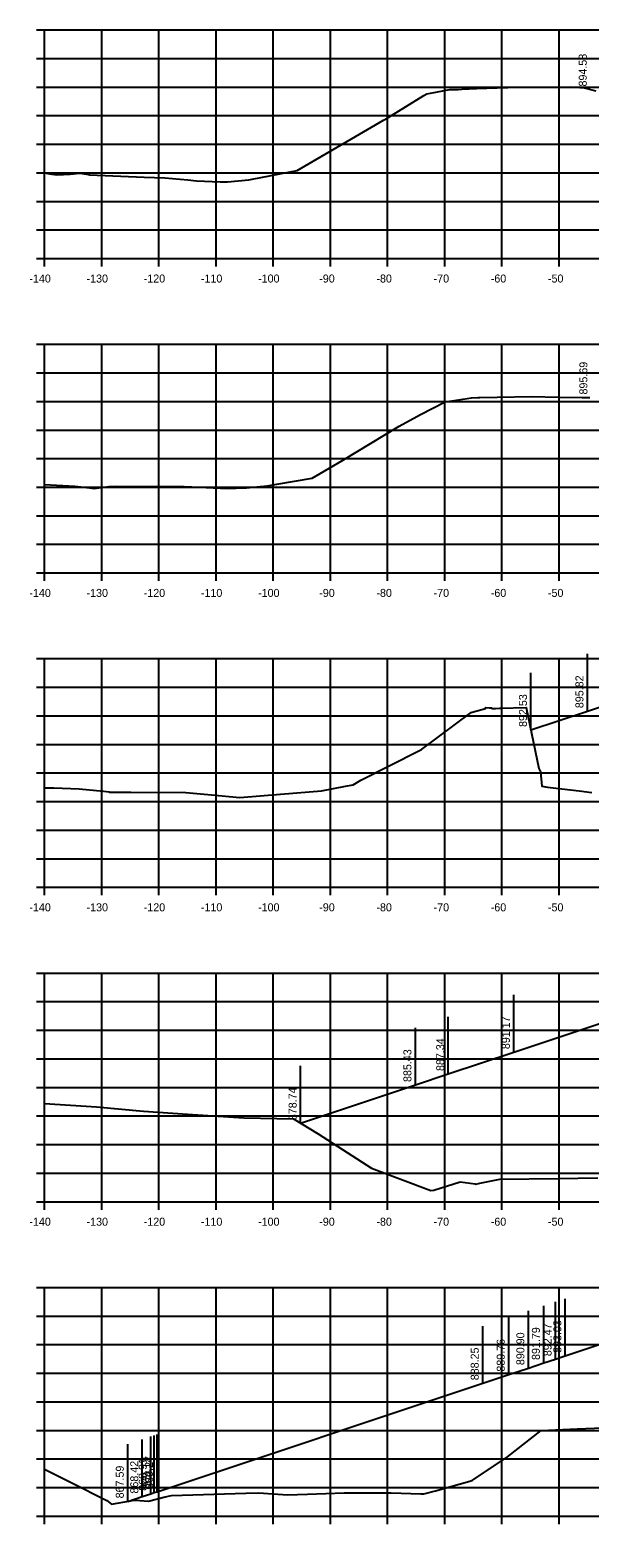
# Model space of a CAD drawing. Extents: x 1098669 to 1198896, y 698679 to 704410.
# Drawn here: x 1111853 to 1111950.8, y 701694.6 to 701956 of the extents above; entities that cross this region are included whole.
import ezdxf

# ---------------------------------------------------------------- set-up
doc = ezdxf.new("R2010")
doc.units = 0
for name, color, linetype in [('59', 7, 'Continuous'), ('Proposed Surface', 7, 'Continuous'), ('R_Axis', 7, 'Continuous'), ('R_Axis Annot', 7, 'Continuous'), ('R_Fin Surface', 7, 'Continuous'), ('R_Grid', 7, 'Continuous'), ('R_Xsect Elev', 7, 'Continuous')]:
    doc.layers.add(name, color=color, linetype=linetype)

msp = doc.modelspace()

# ---------------------------------------------------------------- linework, layer by layer
at = {"layer": 'Proposed Surface'}
for points in [[(1111855.55, 701931.03), (1111856.41, 701930.87), (1111857.69, 701930.65), (1111860, 701930.8), (1111861.69, 701930.98), (1111862.89, 701930.78), (1111863.41, 701930.66), (1111872.98, 701930.25), (1111876.57, 701930.13), (1111880.63, 701929.79), (1111882.09, 701929.64), (1111886.24, 701929.47), (1111887.4, 701929.42), (1111887.53, 701929.44), (1111891.26, 701929.8), (1111891.83, 701929.9), (1111899.74, 701931.41), (1111914.84, 701940.21), (1111915.49, 701940.59), (1111921.87, 701944.52), (1111922.42, 701944.84), (1111923.05, 701944.96), (1111926.42, 701945.57), (1111927.9, 701945.61), (1111928.5, 701945.64), (1111931.1, 701945.75), (1111938.38, 701945.99), (1111940.71, 701946.02), (1111947.5, 701946.08), (1111949.15, 701945.93), (1111949.94, 701945.88), (1111951.98, 701945.39)], [(1111855.55, 701876.51), (1111860.83, 701876.18), (1111863.39, 701875.93), (1111864.23, 701875.8), (1111865.04, 701875.92), (1111866.87, 701876.17), (1111867.73, 701876.16), (1111868.09, 701876.2), (1111879.29, 701876.12), (1111879.96, 701876.12), (1111881.3, 701876.07), (1111887.56, 701875.81), (1111890.59, 701875.9), (1111890.72, 701875.9), (1111890.84, 701875.91), (1111894.49, 701876.29), (1111896.16, 701876.57), (1111902.37, 701877.59), (1111907.51, 701880.65), (1111917.59, 701886.73), (1111921.28, 701888.72), (1111925.61, 701890.98), (1111928.69, 701891.45), (1111930.24, 701891.68), (1111931.3, 701891.69), (1111931.65, 701891.69), (1111934.73, 701891.76), (1111940.72, 701891.9), (1111945.44, 701891.8), (1111949.59, 701891.74), (1111950.9, 701891.74)], [(1111855.55, 701823.45), (1111857.18, 701823.43), (1111861.59, 701823.23), (1111865.84, 701822.82), (1111866.35, 701822.81), (1111866.82, 701822.74), (1111866.84, 701822.69), (1111870.62, 701822.67), (1111880.28, 701822.63), (1111884.72, 701822.23), (1111889.68, 701821.75), (1111896.83, 701822.34), (1111904.01, 701822.92), (1111908.16, 701823.72), (1111909.51, 701823.97), (1111910.88, 701824.75), (1111921.1, 701829.94), (1111921.45, 701830.16), (1111930.17, 701836.61), (1111930.19, 701836.61), (1111930.33, 701836.66), (1111932.67, 701837.31), (1111932.75, 701837.48), (1111933.37, 701837.4), (1111933.69, 701837.41), (1111933.75, 701837.31), (1111934.39, 701837.31), (1111935.1, 701837.38), (1111935.3, 701837.39), (1111939.8, 701837.48), (1111942.01, 701826.83), (1111942.27, 701826.22), (1111942.51, 701823.73), (1111943.49, 701823.54), (1111949.06, 701822.9), (1111951.26, 701822.61)], [(1111855.55, 701768.2), (1111864.64, 701767.62), (1111872.86, 701766.88), (1111880.52, 701766.36), (1111890.37, 701765.69), (1111899.11, 701765.5), (1111903.4, 701762.91), (1111912.71, 701756.88), (1111923.1, 701752.98), (1111923.65, 701753.02), (1111928.23, 701754.48), (1111930.87, 701754.13), (1111930.97, 701754.12), (1111931.67, 701754.26), (1111935.2, 701754.99), (1111945.38, 701755.1), (1111952.3, 701755.23)], [(1111855.55, 701704.22), (1111860.2, 701701.9), (1111866.41, 701698.77), (1111867.27, 701698.14), (1111870.6, 701698.69), (1111871.15, 701698.81), (1111871.43, 701698.79), (1111873.71, 701698.67), (1111876.63, 701699.4), (1111877.74, 701699.63), (1111890.77, 701700.03), (1111893.04, 701700.09), (1111894.63, 701699.98), (1111898.03, 701699.76), (1111901.53, 701699.86), (1111907.94, 701700.12), (1111908.08, 701700.12), (1111916.17, 701700.08), (1111921.35, 701699.95), (1111921.9, 701699.91), (1111923.9, 701700.47), (1111930.31, 701702.27), (1111936.52, 701706.4), (1111942.38, 701711.03), (1111948.71, 701711.3), (1111953.23, 701711.49)]]:
    msp.add_lwpolyline(points, dxfattribs=at)
at = {"layer": 'R_Axis'}
for p, q in [((1111854.15, 701956.03), (1111855.55, 701956.03)), ((1111855.55, 701916.03), (1111855.55, 701956.03)), ((1111854.15, 701951.03), (1111855.55, 701951.03)), ((1111854.15, 701946.03), (1111855.55, 701946.03)), ((1111854.15, 701941.03), (1111855.55, 701941.03)), ((1111854.15, 701936.03), (1111855.55, 701936.03)), ((1111854.15, 701931.03), (1111855.55, 701931.03)), ((1111854.15, 701926.03), (1111855.55, 701926.03)), ((1111854.15, 701921.03), (1111855.55, 701921.03)), ((1111854.15, 701916.03), (1111855.55, 701916.03)), ((1111855.55, 701916.03), (1112135.55, 701916.03)), ((1111855.55, 701914.63), (1111855.55, 701916.03)), ((1111865.55, 701914.63), (1111865.55, 701916.03)), ((1111875.55, 701914.63), (1111875.55, 701916.03)), ((1111885.55, 701914.63), (1111885.55, 701916.03)), ((1111895.55, 701914.63), (1111895.55, 701916.03)), ((1111905.55, 701914.63), (1111905.55, 701916.03)), ((1111915.55, 701914.63), (1111915.55, 701916.03)), ((1111925.55, 701914.63), (1111925.55, 701916.03)), ((1111935.55, 701914.63), (1111935.55, 701916.03)), ((1111945.55, 701914.63), (1111945.55, 701916.03)), ((1111854.15, 701901.03), (1111855.55, 701901.03)), ((1111855.55, 701861.03), (1111855.55, 701901.03)), ((1111854.15, 701896.03), (1111855.55, 701896.03)), ((1111854.15, 701891.03), (1111855.55, 701891.03)), ((1111854.15, 701886.03), (1111855.55, 701886.03)), ((1111854.15, 701881.03), (1111855.55, 701881.03)), ((1111854.15, 701876.03), (1111855.55, 701876.03)), ((1111854.15, 701871.03), (1111855.55, 701871.03)), ((1111854.15, 701866.03), (1111855.55, 701866.03)), ((1111854.15, 701861.03), (1111855.55, 701861.03)), ((1111855.55, 701861.03), (1112135.55, 701861.03)), ((1111855.55, 701859.63), (1111855.55, 701861.03)), ((1111865.55, 701859.63), (1111865.55, 701861.03)), ((1111875.55, 701859.63), (1111875.55, 701861.03)), ((1111885.55, 701859.63), (1111885.55, 701861.03)), ((1111895.55, 701859.63), (1111895.55, 701861.03)), ((1111905.55, 701859.63), (1111905.55, 701861.03)), ((1111915.55, 701859.63), (1111915.55, 701861.03)), ((1111925.55, 701859.63), (1111925.55, 701861.03)), ((1111935.55, 701859.63), (1111935.55, 701861.03)), ((1111945.55, 701859.63), (1111945.55, 701861.03)), ((1111854.15, 701846.03), (1111855.55, 701846.03)), ((1111855.55, 701806.03), (1111855.55, 701846.03)), ((1111854.15, 701841.03), (1111855.55, 701841.03)), ((1111854.15, 701836.03), (1111855.55, 701836.03)), ((1111854.15, 701831.03), (1111855.55, 701831.03)), ((1111854.15, 701826.03), (1111855.55, 701826.03)), ((1111854.15, 701821.03), (1111855.55, 701821.03)), ((1111854.15, 701816.03), (1111855.55, 701816.03)), ((1111854.15, 701811.03), (1111855.55, 701811.03)), ((1111854.15, 701806.03), (1111855.55, 701806.03)), ((1111855.55, 701806.03), (1112135.55, 701806.03)), ((1111855.55, 701804.63), (1111855.55, 701806.03)), ((1111865.55, 701804.63), (1111865.55, 701806.03)), ((1111875.55, 701804.63), (1111875.55, 701806.03)), ((1111885.55, 701804.63), (1111885.55, 701806.03)), ((1111895.55, 701804.63), (1111895.55, 701806.03)), ((1111905.55, 701804.63), (1111905.55, 701806.03)), ((1111915.55, 701804.63), (1111915.55, 701806.03)), ((1111925.55, 701804.63), (1111925.55, 701806.03)), ((1111935.55, 701804.63), (1111935.55, 701806.03)), ((1111945.55, 701804.63), (1111945.55, 701806.03)), ((1111854.15, 701791.03), (1111855.55, 701791.03)), ((1111855.55, 701751.03), (1111855.55, 701791.03)), ((1111854.15, 701786.03), (1111855.55, 701786.03)), ((1111854.15, 701781.03), (1111855.55, 701781.03)), ((1111854.15, 701776.03), (1111855.55, 701776.03)), ((1111854.15, 701771.03), (1111855.55, 701771.03)), ((1111854.15, 701766.03), (1111855.55, 701766.03)), ((1111854.15, 701761.03), (1111855.55, 701761.03)), ((1111854.15, 701756.03), (1111855.55, 701756.03)), ((1111854.15, 701751.03), (1111855.55, 701751.03)), ((1111855.55, 701751.03), (1112135.55, 701751.03)), ((1111855.55, 701749.63), (1111855.55, 701751.03)), ((1111865.55, 701749.63), (1111865.55, 701751.03)), ((1111875.55, 701749.63), (1111875.55, 701751.03)), ((1111885.55, 701749.63), (1111885.55, 701751.03)), ((1111895.55, 701749.63), (1111895.55, 701751.03)), ((1111905.55, 701749.63), (1111905.55, 701751.03)), ((1111915.55, 701749.63), (1111915.55, 701751.03)), ((1111925.55, 701749.63), (1111925.55, 701751.03)), ((1111935.55, 701749.63), (1111935.55, 701751.03)), ((1111945.55, 701749.63), (1111945.55, 701751.03)), ((1111854.15, 701736.03), (1111855.55, 701736.03)), ((1111855.55, 701696.03), (1111855.55, 701736.03)), ((1111854.15, 701731.03), (1111855.55, 701731.03)), ((1111854.15, 701726.03), (1111855.55, 701726.03)), ((1111854.15, 701721.03), (1111855.55, 701721.03)), ((1111854.15, 701716.03), (1111855.55, 701716.03)), ((1111854.15, 701711.03), (1111855.55, 701711.03)), ((1111854.15, 701706.03), (1111855.55, 701706.03)), ((1111854.15, 701701.03), (1111855.55, 701701.03)), ((1111854.15, 701696.03), (1111855.55, 701696.03)), ((1111855.55, 701696.03), (1112135.55, 701696.03)), ((1111855.55, 701694.63), (1111855.55, 701696.03)), ((1111865.55, 701694.63), (1111865.55, 701696.03)), ((1111875.55, 701694.63), (1111875.55, 701696.03)), ((1111885.55, 701694.63), (1111885.55, 701696.03)), ((1111895.55, 701694.63), (1111895.55, 701696.03)), ((1111905.55, 701694.63), (1111905.55, 701696.03)), ((1111915.55, 701694.63), (1111915.55, 701696.03)), ((1111925.55, 701694.63), (1111925.55, 701696.03)), ((1111935.55, 701694.63), (1111935.55, 701696.03)), ((1111945.55, 701694.63), (1111945.55, 701696.03))]:
    msp.add_line(p, q, dxfattribs=at)
at = {"layer": 'R_Fin Surface'}
for points in [[(1111940.62, 701833.56), (1111950.5, 701836.85), (1111954.69, 701838.25), (1111958.75, 701839.6), (1111972.05, 701844.04), (1111977.05, 701843.94), (1111980.05, 701843.88), (1111980.55, 701843.88), (1111981.55, 701843.4), (1111995.55, 701843.68), (1112009.55, 701843.4), (1112010.55, 701843.88), (1112011.05, 701843.88), (1112014.05, 701843.94), (1112019.05, 701844.04), (1112106.87, 701814.76)], [(1111900.33, 701764.77), (1111920.41, 701771.45), (1111926.15, 701773.37), (1111937.63, 701777.2), (1111972.05, 701788.68), (1111977.05, 701788.58), (1111980.05, 701788.52), (1111980.55, 701788.52), (1111981.55, 701788.04), (1111995.55, 701788.32), (1112009.55, 701788.04), (1112010.55, 701788.52), (1112011.05, 701788.52), (1112014.05, 701788.58), (1112019.05, 701788.68), (1112093.91, 701763.73)], [(1111870.1, 701698.61), (1111872.63, 701699.45), (1111874.11, 701699.94), (1111874.74, 701700.15), (1111875.21, 701700.3), (1111932.18, 701719.27), (1111936.73, 701720.78), (1111940.17, 701721.92), (1111942.88, 701722.82), (1111944.92, 701723.49), (1111946.63, 701724.06), (1111962.48, 701729.37)]]:
    msp.add_lwpolyline(points, dxfattribs=at)
at = {"layer": 'R_Grid'}
for p, q in [((1111855.55, 701956.03), (1112135.55, 701956.03)), ((1111855.55, 701916.03), (1111855.55, 701956.03)), ((1111865.55, 701916.03), (1111865.55, 701956.03)), ((1111875.55, 701916.03), (1111875.55, 701956.03)), ((1111885.55, 701916.03), (1111885.55, 701956.03)), ((1111895.55, 701916.03), (1111895.55, 701956.03)), ((1111905.55, 701916.03), (1111905.55, 701956.03)), ((1111915.55, 701916.03), (1111915.55, 701956.03)), ((1111925.55, 701916.03), (1111925.55, 701956.03)), ((1111935.55, 701916.03), (1111935.55, 701956.03)), ((1111945.55, 701916.03), (1111945.55, 701956.03)), ((1111855.55, 701951.03), (1112135.55, 701951.03)), ((1111855.55, 701946.03), (1112135.55, 701946.03)), ((1111855.55, 701941.03), (1112135.55, 701941.03)), ((1111855.55, 701936.03), (1112135.55, 701936.03)), ((1111855.55, 701931.03), (1112135.55, 701931.03)), ((1111855.55, 701926.03), (1112135.55, 701926.03)), ((1111855.55, 701921.03), (1112135.55, 701921.03)), ((1111855.55, 701916.03), (1112135.55, 701916.03)), ((1111855.55, 701901.03), (1112135.55, 701901.03)), ((1111855.55, 701861.03), (1111855.55, 701901.03)), ((1111865.55, 701861.03), (1111865.55, 701901.03)), ((1111875.55, 701861.03), (1111875.55, 701901.03)), ((1111885.55, 701861.03), (1111885.55, 701901.03)), ((1111895.55, 701861.03), (1111895.55, 701901.03)), ((1111905.55, 701861.03), (1111905.55, 701901.03)), ((1111915.55, 701861.03), (1111915.55, 701901.03)), ((1111925.55, 701861.03), (1111925.55, 701901.03)), ((1111935.55, 701861.03), (1111935.55, 701901.03)), ((1111945.55, 701861.03), (1111945.55, 701901.03)), ((1111855.55, 701896.03), (1112135.55, 701896.03)), ((1111855.55, 701891.03), (1112135.55, 701891.03)), ((1111855.55, 701886.03), (1112135.55, 701886.03)), ((1111855.55, 701881.03), (1112135.55, 701881.03)), ((1111855.55, 701876.03), (1112135.55, 701876.03)), ((1111855.55, 701871.03), (1112135.55, 701871.03)), ((1111855.55, 701866.03), (1112135.55, 701866.03)), ((1111855.55, 701861.03), (1112135.55, 701861.03)), ((1111855.55, 701846.03), (1112135.55, 701846.03)), ((1111855.55, 701806.03), (1111855.55, 701846.03)), ((1111865.55, 701806.03), (1111865.55, 701846.03)), ((1111875.55, 701806.03), (1111875.55, 701846.03)), ((1111885.55, 701806.03), (1111885.55, 701846.03)), ((1111895.55, 701806.03), (1111895.55, 701846.03)), ((1111905.55, 701806.03), (1111905.55, 701846.03)), ((1111915.55, 701806.03), (1111915.55, 701846.03)), ((1111925.55, 701806.03), (1111925.55, 701846.03)), ((1111935.55, 701806.03), (1111935.55, 701846.03)), ((1111945.55, 701806.03), (1111945.55, 701846.03)), ((1111855.55, 701841.03), (1112135.55, 701841.03)), ((1111855.55, 701836.03), (1112135.55, 701836.03)), ((1111855.55, 701831.03), (1112135.55, 701831.03)), ((1111855.55, 701826.03), (1112135.55, 701826.03)), ((1111855.55, 701821.03), (1112135.55, 701821.03)), ((1111855.55, 701816.03), (1112135.55, 701816.03)), ((1111855.55, 701811.03), (1112135.55, 701811.03)), ((1111855.55, 701806.03), (1112135.55, 701806.03)), ((1111855.55, 701791.03), (1112135.55, 701791.03)), ((1111855.55, 701751.03), (1111855.55, 701791.03)), ((1111865.55, 701751.03), (1111865.55, 701791.03)), ((1111875.55, 701751.03), (1111875.55, 701791.03)), ((1111885.55, 701751.03), (1111885.55, 701791.03)), ((1111895.55, 701751.03), (1111895.55, 701791.03)), ((1111905.55, 701751.03), (1111905.55, 701791.03)), ((1111915.55, 701751.03), (1111915.55, 701791.03)), ((1111925.55, 701751.03), (1111925.55, 701791.03)), ((1111935.55, 701751.03), (1111935.55, 701791.03)), ((1111945.55, 701751.03), (1111945.55, 701791.03)), ((1111855.55, 701786.03), (1112135.55, 701786.03)), ((1111855.55, 701781.03), (1112135.55, 701781.03)), ((1111855.55, 701776.03), (1112135.55, 701776.03)), ((1111855.55, 701771.03), (1112135.55, 701771.03)), ((1111855.55, 701766.03), (1112135.55, 701766.03)), ((1111855.55, 701761.03), (1112135.55, 701761.03)), ((1111855.55, 701756.03), (1112135.55, 701756.03)), ((1111855.55, 701751.03), (1112135.55, 701751.03)), ((1111855.55, 701736.03), (1112135.55, 701736.03)), ((1111855.55, 701696.03), (1111855.55, 701736.03)), ((1111865.55, 701696.03), (1111865.55, 701736.03)), ((1111875.55, 701696.03), (1111875.55, 701736.03)), ((1111885.55, 701696.03), (1111885.55, 701736.03)), ((1111895.55, 701696.03), (1111895.55, 701736.03)), ((1111905.55, 701696.03), (1111905.55, 701736.03)), ((1111915.55, 701696.03), (1111915.55, 701736.03)), ((1111925.55, 701696.03), (1111925.55, 701736.03)), ((1111935.55, 701696.03), (1111935.55, 701736.03)), ((1111945.55, 701696.03), (1111945.55, 701736.03)), ((1111855.55, 701731.03), (1112135.55, 701731.03)), ((1111855.55, 701726.03), (1112135.55, 701726.03)), ((1111855.55, 701721.03), (1112135.55, 701721.03)), ((1111855.55, 701716.03), (1112135.55, 701716.03)), ((1111855.55, 701711.03), (1112135.55, 701711.03)), ((1111855.55, 701706.03), (1112135.55, 701706.03)), ((1111855.55, 701701.03), (1112135.55, 701701.03)), ((1111855.55, 701696.03), (1112135.55, 701696.03))]:
    msp.add_line(p, q, dxfattribs=at)
at = {"layer": 'R_Xsect Elev'}
for p, q in [((1111950.5, 701836.85), (1111950.5, 701846.85)), ((1111940.62, 701833.56), (1111940.62, 701843.56)), ((1111937.63, 701777.2), (1111937.63, 701787.2)), ((1111926.15, 701773.37), (1111926.15, 701783.37)), ((1111920.41, 701771.45), (1111920.41, 701781.45)), ((1111900.33, 701764.77), (1111900.33, 701774.77)), ((1111946.63, 701724.06), (1111946.63, 701734.06)), ((1111940.17, 701721.92), (1111940.17, 701731.92)), ((1111942.88, 701722.82), (1111942.88, 701732.82)), ((1111944.92, 701723.49), (1111944.92, 701733.49)), ((1111932.18, 701719.27), (1111932.18, 701729.27)), ((1111936.73, 701720.78), (1111936.73, 701730.78)), ((1111874.74, 701700.15), (1111874.74, 701710.15)), ((1111875.21, 701700.3), (1111875.21, 701710.3)), ((1111870.1, 701698.61), (1111870.1, 701708.61)), ((1111872.63, 701699.45), (1111872.63, 701709.45)), ((1111874.11, 701699.94), (1111874.11, 701709.94))]:
    msp.add_line(p, q, dxfattribs=at)

# ---------------------------------------------------------------- texts
at = {"layer": '59'}
for s, p in [(' 894.58', (1111950.38, 701945.6)), (' 895.69', (1111950.49, 701891.72)), (' 895.82', (1111949.8, 701836.85)), (' 892.53', (1111939.92, 701833.56)), (' 891.17', (1111936.93, 701777.2)), (' 887.34', (1111925.45, 701773.37)), (' 885.43', (1111919.71, 701771.45)), (' 878.74', (1111899.63, 701764.77)), (' 891.79', (1111942.18, 701722.82)), (' 892.47', (1111944.22, 701723.49)), (' 893.03', (1111945.93, 701724.06)), (' 889.76', (1111936.03, 701720.78)), (' 890.90', (1111939.47, 701721.92)), (' 888.25', (1111931.48, 701719.27)), (' 868.42', (1111871.93, 701699.45)), (' 868.91', (1111873.41, 701699.94)), (' 869.12', (1111874.04, 701700.15)), (' 869.27', (1111874.51, 701700.3)), (' 867.59', (1111869.4, 701698.61))]:
    msp.add_text(s, height=1.4, rotation=90, dxfattribs=at).set_placement(p)
at = {"layer": 'R_Axis Annot'}
for s, p in [('-140', (1111852.89, 701911.83)), ('-130', (1111862.89, 701911.83)), ('-120', (1111872.89, 701911.83)), ('-110', (1111882.89, 701911.83)), ('-100', (1111892.89, 701911.83)), ('-90', (1111903.59, 701911.83)), ('-80', (1111913.59, 701911.83)), ('-70', (1111923.59, 701911.83)), ('-60', (1111933.59, 701911.83)), ('-50', (1111943.59, 701911.83)), ('-140', (1111852.89, 701856.83)), ('-130', (1111862.89, 701856.83)), ('-120', (1111872.89, 701856.83)), ('-110', (1111882.89, 701856.83)), ('-100', (1111892.89, 701856.83)), ('-90', (1111903.59, 701856.83)), ('-80', (1111913.59, 701856.83)), ('-70', (1111923.59, 701856.83)), ('-60', (1111933.59, 701856.83)), ('-50', (1111943.59, 701856.83)), ('-140', (1111852.89, 701801.83)), ('-130', (1111862.89, 701801.83)), ('-120', (1111872.89, 701801.83)), ('-110', (1111882.89, 701801.83)), ('-100', (1111892.89, 701801.83)), ('-90', (1111903.59, 701801.83)), ('-80', (1111913.59, 701801.83)), ('-70', (1111923.59, 701801.83)), ('-60', (1111933.59, 701801.83)), ('-50', (1111943.59, 701801.83)), ('-140', (1111852.89, 701746.83)), ('-130', (1111862.89, 701746.83)), ('-120', (1111872.89, 701746.83)), ('-110', (1111882.89, 701746.83)), ('-100', (1111892.89, 701746.83)), ('-90', (1111903.59, 701746.83)), ('-80', (1111913.59, 701746.83)), ('-70', (1111923.59, 701746.83)), ('-60', (1111933.59, 701746.83)), ('-50', (1111943.59, 701746.83))]:
    msp.add_text(s, height=1.4, dxfattribs=at).set_placement(p)

doc.saveas('drawing.dxf')
